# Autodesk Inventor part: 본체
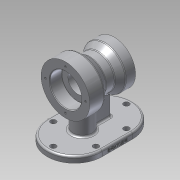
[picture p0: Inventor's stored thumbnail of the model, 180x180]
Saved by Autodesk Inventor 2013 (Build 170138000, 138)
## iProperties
Created: 2020-01
Part Number: 본체
Material: 알루미늄 6061
Document SubType Name: Modeling
Designer: Administrator
Mass: 941.582 g
Surface Area: 654.888 cm^2
Volume: 347.447 cm^3
Density: 2.71 g/cm^3
Author: Administrator
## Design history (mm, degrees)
sketch "스케치1"
  geometry: L1 (0, 0)-(0, 26); L2 (0, 40)-(24, 40); L3 (24, 40)-(38.897, 27.5); L4 (38.897, 27.5)-(53.289, 27.5); L5 (53.289, 27.5)-(64, 35); L6 (64, 35)-(80, 35); L7 (80, 35)-(80, 20); L8 (80, 0)-(0, 0); L9 (0, 26)-(20, 26); L10 (20, 26)-(20, 16); L11 (20, 16)-(63, 16); L12 (63, 16)-(63, 20); L13 (63, 20)-(80, 20); L14 (0, 26)-(0, 40); L15 (80, 20)-(80, 0)
  constraints: 30 end point, 10 parallel, 5 perpendicular, 2 vertical
  dimensions: "d15" = 80 diameter of L2 L8; "d17" = 80 distance of L8.start L1.start; "d18" = 40 deg angle of L3 L4; "d19" = 35 deg angle of L5 L4; "d21" = 70 diameter of L6 L8; "d22" = 24 distance of L2.start L2.end; "d23" = 16 distance of L5.end L6.end; "d24" = 55 diameter of L4 L8; "d25" = 20 distance of L1.end L9.end; "d26" = 17 distance of L12.end L7.end; "d27" = 52 diameter of L9 L8; "d28" = 32 diameter of L11 L8; "d29" = 40 diameter of L13 L8
revolve "회전1" sketch "스케치1" stored, may be unused: angle "d30" = 90 deg
fillet "모깎기1" dims "d31" = 0.3
chamfer "모따기1" distance "d32" = 1; stored, may be unused: second distance "d33" = 2, angle "d34" = 45 deg
sketch "스케치2"
  geometry: C1 r 40 at (0, 0) reference; 1 further point
  constraints: 1 vertical alignment
  dimensions: "d35" = 33 distance of C1.centre point (0, 33)
hole "구멍1" sketch "스케치2" at (0, 33) diameter "d36" = 3.242; stored, may be unused: countersink angle "d40" = 90 deg, drill point angle "d42" = 118 deg; dims "d37" = 9, "d38" = 4, "d39" = 2, "d41" = 11
sketch "스케치3"
  geometry: C1 r 35 at (0, 0) reference; 1 further point
  constraints: 1 vertical alignment
  dimensions: "d46" = 27.5 distance of C1.centre point (0, 27.5)
hole "구멍2" sketch "스케치3" at (0, 27.5) diameter "d47" = 3.242; stored, may be unused: countersink angle "d51" = 90 deg, drill point angle "d53" = 118 deg; dims "d48" = 9, "d49" = 4, "d50" = 2, "d52" = 11
sketch "스케치4"
  geometry: L1 (-30, -70)-(110, -70); L2 (110, -70)-(110, -80); L3 (110, -80)-(-30, -80); L4 (-30, -80)-(-30, -70); 1 further point
  constraints: 8 end point, 2 parallel, 1 horizontal, 1 perpendicular
  dimensions: "d57" = 30 distance from line of point (0, 0) L4; "d58" = 140 distance of L2.end L3.end; "d59" = 10 distance of L1.end L2.end; "d60" = 80 distance from line of point (0, 0) L3
extrude "돌출1" join sketch "스케치4" stored distance "d61" = 90; taper "d62" = 0 deg
fillet "모깎기2" dims "d63" = 45
sketch "스케치5"
  geometry: L1 (50, -90)-(0, -90) reference; L2 (28.199, -40)-(55, -40); L3 (55, -40)-(55, -50); L4 (55, -50)-(28.199, -50); L5 (13, -45)-(-45, -45); L6 (65, -80)-(65, -10) reference; A1 r 45 centre (50, -45) between (50, -90) and (50, 0) reference; A2 r 45 centre (0, -45) between (0, 0) and (0, -90) reference; A3 r 16 centre (13, -45) between (28.199, -40) and (28.199, -50); 2 further points
  constraints: 8 end point, 3 horizontal alignment, 3 parallel, 3 point on circle, 1 centre point, 1 midpoint, 1 perpendicular
  dimensions: "d64" = 32 diameter of A3; "d66" = 10 distance of L2.end L3.end; "d67" = 58 distance of L5.start L5.end; "d68" = 10 distance between parallel lines of L6 L3
extrude "돌출2" join sketch "스케치5" stored distance "d69" = 90; taper "d70" = 0 deg
sketch "스케치6"
  geometry: L1 (0, 0)-(50, 0) reference; L2 (50, -90)-(0, -90) reference; L3 (50, -80)-(0, -80); L4 (0, -10)-(50, -10); L5 (50, 0)-(0, 0) reference; L6 (25, 0)-(25, -90); A1 r 45 centre (50, -45) between (50, -90) and (50, 0) reference; A2 r 45 centre (0, -45) between (0, 0) and (0, -90) reference; A3 r 35 centre (50, -45) between (50, -80) and (50, -10); A4 r 35 centre (0, -45) between (0, -10) and (0, -80); 7 further points
  constraints: 6 end point, 6 point on circle, 4 point on line, 2 centre point, 2 midpoint, 2 vertical alignment, 3 other
  dimensions: "d71" = 10 distance between parallel lines of L1 L4; "d72" = 25 distance from line of L6 point (0, -10); "d73" = 25 distance from line of L6 point (50, -10)
hole "구멍3" sketch "스케치6" at (-35, -45), (85, -45), (0, -10), (50, -10), (0, -80), (50, -80) diameter "d74" = 9; stored, may be unused: countersink angle "d78" = 90 deg, drill point angle "d80" = 0 deg; dims "d75" = 9, "d76" = 4, "d77" = 2, "d79" = 11
sketch "스케치7"
  geometry: L1 (15, -80)-(65, -80) reference; L2 (-30, -70)-(-30, -80) reference; 2 further points
  constraints: 1 other
  dimensions: "d83" = 4 distance from line of point (40, -76) L1; "d84" = 70 distance from line of L2 point (40, -76)
feature "엠보싱1" sketch "스케치7" dims "d32" = 1, "d85" = 0.5, "d86" = 0
fillet "모깎기3" dims "d87" = 3
fillet "모깎기4" dims "d88" = 3
fillet "모깎기5" dims "d89" = 3
node "솔리드1"
pattern_circular "원형 패턴1" dims angle "d44" = 360 deg
pattern_circular "원형 패턴2" dims angle "d55" = 360 deg
